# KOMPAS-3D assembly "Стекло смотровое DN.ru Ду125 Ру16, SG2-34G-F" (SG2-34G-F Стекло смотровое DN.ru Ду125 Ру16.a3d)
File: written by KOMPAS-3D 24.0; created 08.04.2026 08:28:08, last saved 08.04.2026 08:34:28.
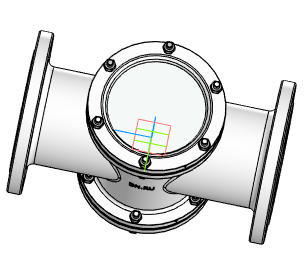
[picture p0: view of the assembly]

Document properties: Автор: Main; Полное имя файла: D:\DN.ru Аутсерс\Стекло смотровое DN.ru\Исходники\Стекло смотровое DN.ru SG2-34G-F тип В ГОСТ 21836-2021 Ду125 Ру16, углеродистая сталь, фланцевое\SG2-34G-F Стекло смотровое DN.ru Ду125 Ру16.a3d

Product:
- Component [detail]: Деталь  | qty 1  | pos. 1  | Масса: 34.683393; Автор: Main; additional columns: Типовые; source file: ДетальДеталь.m3d
- Component [detail]: Стекло  | qty 2  | pos. 2  | Масса: 1.895451; Автор: Main; source file: СтеклоСтекло.m3d
- Component [detail]: ANSI B18.2.4.2M - M10x1,5 - 16  | designation ANSI B18.2.4.2M - M10x1,5  | qty 26  | pos. 3  | Масса: 0.012122; Комментарий: Типы метрических   шестигранных гаек   2; Автор: Main; additional columns: Сталь, мягкая; source file: ANSI B18.2.4.2M - M10x1,5ANSI B18.2.4.2M - M10x1,5 - 16.m3d
- Part/product: Стекло смотровое DN.ru Ду125 Ру16  | designation SG2-34G-F
    Масса: 36
    Раздел спецификации: Прочие изделия
    Примечание: D500-00088

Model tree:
1. Массив по концентрической сетке:1  (labels: Грань.Твердое тело1; Грань.Solid1; Ребро.Твердое тело1; Ребро.Solid1)  (6 pattern instances)
     Шаг 2 = 360

Expressions: SG2-34G-F
Referenced files in D:\DN.ru Аутсерс\Стекло смотровое DN.ru\Исходники\Стекло смотровое DN.ru SG2-34G-F тип В ГОСТ 21836-2021 Ду125 Ру16, углеродистая сталь, фланцевое\: ДетальДеталь.m3d, СтеклоСтекло.m3d, ANSI B18.2.4.2M - M10x1,5ANSI B18.2.4.2M - M10x1,5 - 16.m3d
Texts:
  Стекло Стекло (1)
  Стекло Стекло (2)
  ANSI B18.2.4.2M - M10x1,5 ANSI B18.2.4.2M - M10x1,5 - 16 (1)
  ANSI B18.2.4.2M - M10x1,5 ANSI B18.2.4.2M - M10x1,5 - 16 (2)
  ANSI B18.2.4.2M - M10x1,5 ANSI B18.2.4.2M - M10x1,5 - 16 (3)
  ANSI B18.2.4.2M - M10x1,5 ANSI B18.2.4.2M - M10x1,5 - 16 (4)
  ANSI B18.2.4.2M - M10x1,5 ANSI B18.2.4.2M - M10x1,5 - 16 (5)
  ANSI B18.2.4.2M - M10x1,5 ANSI B18.2.4.2M - M10x1,5 - 16 (6)
  Ось Z.Начало координат
  Ось X.Начало координат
